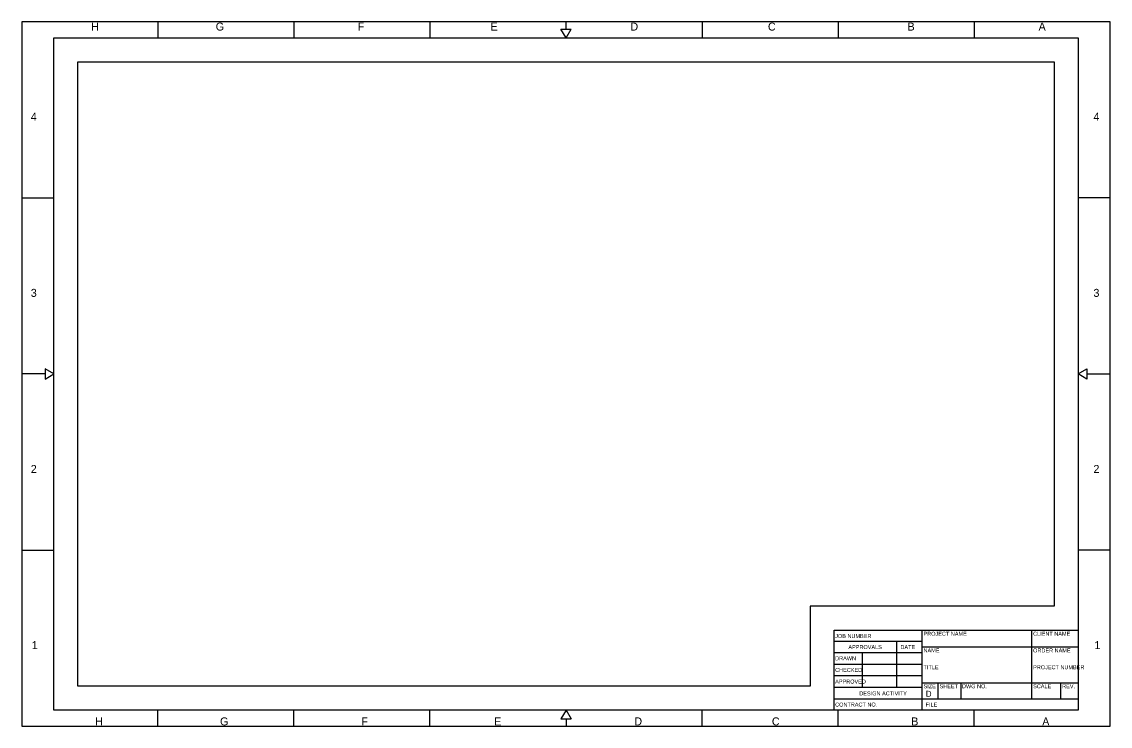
# Model space of a CAD drawing. Extents: x 0 to 2.83, y 0 to 1.83.
import ezdxf

# ---------------------------------------------------------------- set-up
doc = ezdxf.new("R2010")
doc.units = 0
for name, color, linetype in [('Border', 7, 'Continuous'), ('BorderPlot', 7, 'Continuous'), ('ClipShape', 7, 'Continuous'), ('TitleBlock', 7, 'Continuous'), ('TitleBlockText', 7, 'Continuous')]:
    doc.layers.add(name, color=color, linetype=linetype)

# ---------------------------------------------------------------- blocks, each defined once
blk = doc.blocks.new('DC-ANSI-D')
at = {"layer": 'Border'}
for p, q in [((0.3542, 1.8333), (0.3542, 1.7917)), ((0.7083, 1.8333), (0.7083, 1.7917)), ((1.0625, 1.8333), (1.0625, 1.7917)), ((1.4167, 1.7917), (1.4036, 1.8143)), ((1.4036, 1.8143), (1.4297, 1.8143)), ((1.4167, 1.8143), (1.4167, 1.8333)), ((1.4167, 1.7917), (1.4297, 1.8143)), ((1.7708, 1.8333), (1.7708, 1.7917)), ((2.125, 1.8333), (2.125, 1.7917)), ((2.4792, 1.8333), (2.4792, 1.7917)), ((0, 1.375), (0.0833, 1.375)), ((2.8333, 1.375), (2.75, 1.375)), ((0.0607, 0.9167), (0, 0.9167)), ((0.0833, 0.9167), (0.0607, 0.9297)), ((0.0607, 0.9297), (0.0607, 0.9036)), ((0.0607, 0.9036), (0.0833, 0.9167)), ((2.75, 0.9167), (2.7726, 0.9297)), ((2.7726, 0.9036), (2.75, 0.9167)), ((2.7726, 0.9297), (2.7726, 0.9036)), ((2.7726, 0.9167), (2.8333, 0.9167)), ((0, 0.4583), (0.0833, 0.4583)), ((2.8333, 0.4583), (2.75, 0.4583)), ((0.3542, 0), (0.3542, 0.0417)), ((0.7083, 0), (0.7083, 0.0417)), ((1.0625, 0), (1.0625, 0.0417)), ((1.4167, 0.0417), (1.4036, 0.0191)), ((1.4167, 0.0417), (1.4297, 0.0191)), ((1.7708, 0), (1.7708, 0.0417)), ((2.125, 0), (2.125, 0.0417)), ((2.4792, 0), (2.4792, 0.0417)), ((1.4036, 0.0191), (1.4297, 0.0191)), ((1.4167, 0.0191), (1.4167, 0))]:
    blk.add_line(p, q, dxfattribs=at)
blk.add_lwpolyline([(2.75, 0.0417), (0.0833, 0.0417), (0.0833, 1.7917), (2.75, 1.7917)], close=True, dxfattribs=at)
at = {"layer": 'BorderPlot'}
blk.add_lwpolyline([(0, 0), (2.8333, 0), (2.8333, 1.8333), (0, 1.8333)], close=True, dxfattribs=at)
at = {"layer": 'ClipShape'}
for p, q in [((0.1458, 0.1042), (0.1458, 1.7292)), ((0.1458, 1.7292), (2.6875, 1.7292)), ((2.6875, 1.7292), (2.6875, 0.3125)), ((2.6875, 0.3125), (2.0525, 0.3125)), ((2.0525, 0.3125), (2.0525, 0.1042)), ((2.0525, 0.1042), (0.1458, 0.1042))]:
    blk.add_line(p, q, dxfattribs=at)
at = {"layer": 'TitleBlock'}
for p, q in [((2.115, 0.0417), (2.115, 0.25)), ((2.115, 0.25), (2.75, 0.25)), ((2.3442, 0.0417), (2.3442, 0.25)), ((2.6293, 0.0717), (2.6293, 0.25)), ((2.115, 0.2217), (2.3442, 0.2217)), ((2.2782, 0.1017), (2.2782, 0.2217)), ((2.3442, 0.2067), (2.75, 0.2067)), ((2.115, 0.1917), (2.3442, 0.1917)), ((2.1883, 0.1017), (2.1883, 0.1917)), ((2.115, 0.1617), (2.3442, 0.1617)), ((2.115, 0.1317), (2.3442, 0.1317)), ((2.3442, 0.1133), (2.75, 0.1133)), ((2.3858, 0.0717), (2.3858, 0.1133)), ((2.4451, 0.0717), (2.4451, 0.1133)), ((2.7049, 0.0717), (2.7049, 0.1133)), ((2.115, 0.1017), (2.3442, 0.1017)), ((2.115, 0.0717), (2.75, 0.0717)), ((2.75, 0.0417), (2.75, 0.0417))]:
    blk.add_line(p, q, dxfattribs=at)
at = {"layer": 'Border'}
for s, p in [('H', (0.1808, 1.8104)), ('G', (0.5049, 1.8104)), ('F', (0.8743, 1.8104)), ('E', (1.2202, 1.8104)), ('D', (1.5843, 1.8104)), ('C', (1.9423, 1.8104)), ('B', (2.3057, 1.8104)), ('A', (2.6468, 1.8104)), ('4', (0.0235, 1.5758)), ('4', (2.7897, 1.5758)), ('3', (0.0235, 1.1174)), ('3', (2.7897, 1.1174)), ('2', (0.0235, 0.6591)), ('2', (2.7897, 0.6591)), ('1', (0.0261, 0.2008)), ('1', (2.7923, 0.2008)), ('H', (0.1912, 0.0021)), ('G', (0.5161, 0.0021)), ('F', (0.8839, 0.0021)), ('E', (1.2298, 0.0021)), ('D', (1.5946, 0.0021)), ('C', (1.9526, 0.0021)), ('B', (2.3153, 0.0021)), ('A', (2.6564, 0.0021))]:
    blk.add_text(s, height=0.0208, dxfattribs=at).set_placement(p)
at = {"layer": 'TitleBlock'}
blk.add_text('D', height=0.0156, dxfattribs=at).set_placement((2.3532, 0.0766))
at = {"layer": 'TitleBlockText'}
for s, height, p in [('JOB NUMBER', 0.01042, (2.1173, 0.2295)), ('PROJECT NAME', 0.010417, (2.3473, 0.2355)), ('CLIENT NAME', 0.010417, (2.6326, 0.2355)), ('APPROVALS', 0.01042, (2.1517, 0.2008)), ('DATE', 0.01042, (2.2872, 0.2008)), ('NAME', 0.01042, (2.3473, 0.1921)), ('ORDER NAME', 0.01042, (2.6326, 0.1921)), ('DRAWN', 0.01042, (2.1173, 0.1715)), ('CHECKED', 0.01042, (2.1173, 0.1413)), ('TITLE', 0.01042, (2.3473, 0.1483)), ('PROJECT NUMBER', 0.010417, (2.6326, 0.1483)), ('APPROVED', 0.01042, (2.1173, 0.1111)), ('DESIGN ACTIVITY', 0.010417, (2.1802, 0.0803)), ('SIZE', 0.01042, (2.3473, 0.0988)), ('SHEET', 0.01042, (2.389, 0.0988)), ('DWG NO.', 0.01042, (2.4474, 0.0988)), ('SCALE', 0.01042, (2.6326, 0.0988)), ('REV.', 0.01042, (2.7082, 0.0988)), ('CONTRACT NO.', 0.010417, (2.1173, 0.0512)), ('FILE', 0.01042, (2.3528, 0.0513))]:
    blk.add_text(s, height=height, dxfattribs=at).set_placement(p)

msp = doc.modelspace()

# ---------------------------------------------------------------- block references
msp.add_blockref('DC-ANSI-D', (0, 0))

doc.saveas('drawing.dxf')
